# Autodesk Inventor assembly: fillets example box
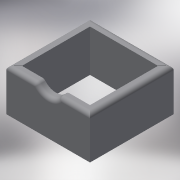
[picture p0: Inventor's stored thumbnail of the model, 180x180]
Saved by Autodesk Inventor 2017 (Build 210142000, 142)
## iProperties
Created: 2017-11
Part Number: fillets example box
Document SubType Name: Assembly
Designer: lshopper
Author: lshopper
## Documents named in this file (4)
- C:\Users\lshopper\Desktop\Inventor Projects\box eamples\New folder\fillets example box.iam
- C:\Users\lshopper\Desktop\Inventor Projects\box eamples\front aa.ipt
- C:\Users\lshopper\Desktop\Inventor Projects\box eamples\back aa.ipt
- C:\Users\lshopper\Desktop\Inventor Projects\box eamples\side aa.ipt
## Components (4 placed, 3 different names)
1. front aa:1 — Mate:1, Mate:2, Mate:3, Mate:4
2. back aa:1 — Mate:5, Mate:6
3. side aa:1 — Mate:3, Mate:4, Mate:5, Mate:6
4. back aa:2 — Mate:1, Mate:2
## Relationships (6: Mate 6)
- Mate:1: front aa:1 ↔ back aa:2
- Mate:2: front aa:1 ↔ back aa:2
- Mate:3: front aa:1 ↔ side aa:1
- Mate:4: front aa:1 ↔ side aa:1
- Mate:5: back aa:1 ↔ side aa:1
- Mate:6: back aa:1 ↔ side aa:1
